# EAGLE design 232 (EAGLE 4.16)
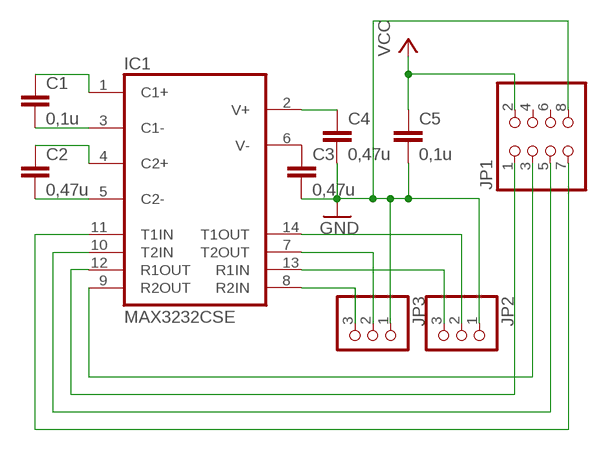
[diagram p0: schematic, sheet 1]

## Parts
C1  0,1u  C-EUC1206  [C1206]
C2  0,47u  C-EUC1206  [C1206]
C3  0,47u  C-EUC1206  [C1206]
C4  0,47u  C-EUC1206  [C1206]
C5  0,1u  C-EUC1206  [C1206]
IC1  MAX3232CSE  [SO16]
JP1  PINHD-2X4  [2X04]
JP2  PINHD-1X3  [1X03]
JP3  PINHD-1X3  [1X03]

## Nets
GND: C3.2 C4.2 C5.2 JP1.8 JP2.1 JP3.1
N$1: C1.2 IC1.3(C1-)
N$2: C1.1 IC1.1(C1+)
N$3: C2.2 IC1.5(C2-)
N$4: C2.1 IC1.4(C2+)
N$5: C4.1 IC1.2(V+)
N$6: C3.1 IC1.6(V-)
N$7: IC1.12(R1OUT) JP1.1
N$8: IC1.9(R2OUT) JP1.3
N$10: IC1.14(T1OUT) JP2.2
N$11: IC1.13(R1IN) JP2.3
N$12: IC1.11(T1IN) JP1.7
N$13: IC1.10(T2IN) JP1.5
N$14: IC1.7(T2OUT) JP3.2
N$15: IC1.8(R2IN) JP3.3
VCC: C5.1 JP1.2
Unconnected: JP1.4 JP1.6

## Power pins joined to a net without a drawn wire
GND: IC1.15(GND)
VCC: IC1.16(VCC)

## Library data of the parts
C1-C5 = rcl:C-EU: CAPACITOR, European symbol
IC1 = maxim:MAX3232*: True RS-232 Transceivers 3.0V to 5.5V, Low-Power up to 1Mbps, Using Four 0.1µF External Capacitors Source: http://pdfserv.maxim-ic.com/en/ds/MAX3222-MAX3241.pdf
JP1 = pinhead:PINHD-2X4: PIN HEADER
JP2 JP3 = pinhead:PINHD-1X3: PIN HEADER

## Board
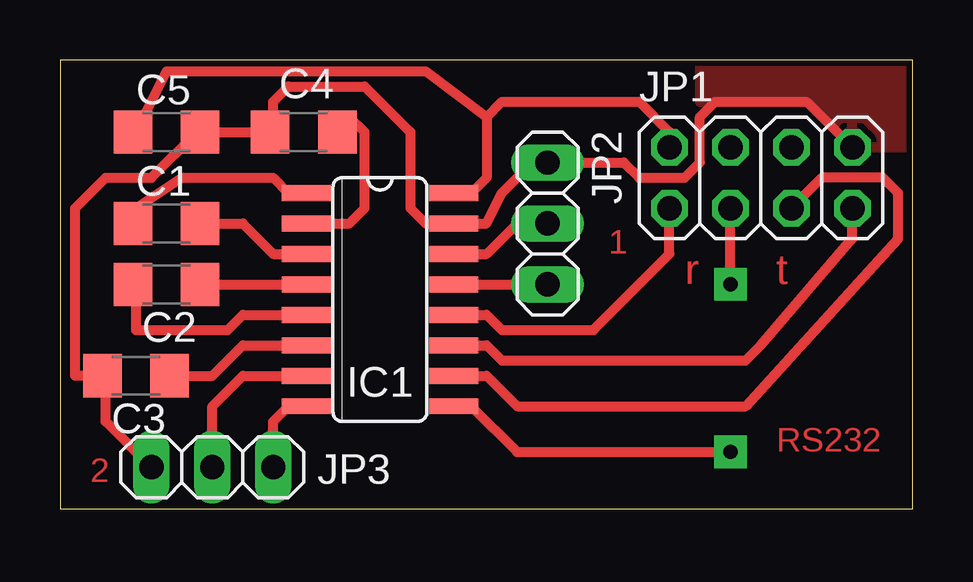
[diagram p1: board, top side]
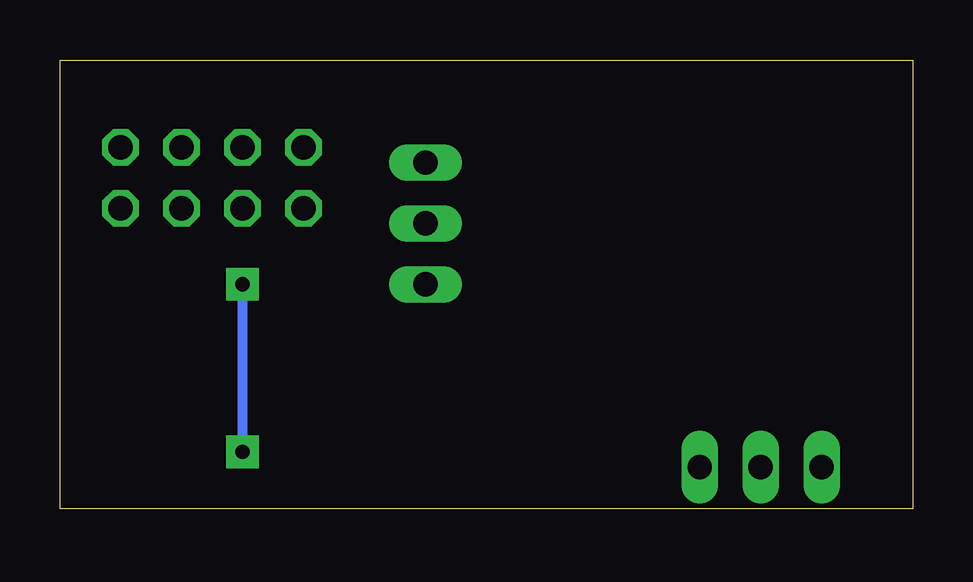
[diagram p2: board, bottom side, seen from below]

Size 35.54 x 18.72 mm. Coordinates in mm from the lower left corner, seen from the top.
Outline: 0,0 35.54,0 35.54,18.72 0,18.72 0,0
Copper layers (1*16): Top 0.035mm / dielectric 1.5mm / Bottom 0.035mm
Design rules "default": minimum track width 10mil, minimum drill 24mil, track to track 8mil, track to pad 8mil, pad to pad 8mil, via to via 8mil, smd to smd 8mil, copper to edge 10mil, drill to drill 8mil, minimum pad ring 10mil, minimum via ring 15mil, stop-mask expansion 4mil, vias tented up to drill 0mil, thermal gap 10mil

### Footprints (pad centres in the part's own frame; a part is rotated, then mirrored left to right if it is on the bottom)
C1206 = smd 1.6 x 1.8: 1 -1.4,0; 2 1.4,0
SO16 = smd 0.66 x 2.032: 1 -4.445,-3.073; 2 -3.175,-3.073; 3 -1.905,-3.073; 4 -0.635,-3.073; 5 0.635,-3.073; 6 1.905,-3.073; 7 3.175,-3.073; 8 4.445,-3.073; 9 4.445,3.073; 10 3.175,3.073; 11 1.905,3.073; 12 0.635,3.073; 13 -0.635,3.073; 14 -1.905,3.073; 15 -3.175,3.073; 16 -4.445,3.073
2X04 = drill 1.016 octagon: 1 -3.81,-1.27; 2 -3.81,1.27; 3 -1.27,-1.27; 4 -1.27,1.27; 5 1.27,-1.27; 6 1.27,1.27; 7 3.81,-1.27; 8 3.81,1.27
1X03 = drill 1.016 long: 1 -2.54,0; 2 0,0; 3 2.54,0

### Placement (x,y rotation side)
C1  4.44,11.9 0 top
C2  4.44,9.36 180 top
C3  3.17,5.55 180 top
C4  10.15,15.71 180 top
C5  4.44,15.71 0 top
IC1  13.33,8.73 270 top
JP1  29.21,13.81 0 top
JP2  20.32,11.9 270 top
JP3  6.35,1.74 0 top

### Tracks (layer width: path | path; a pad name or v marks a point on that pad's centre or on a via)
GND
  Top 0.406: JP1.8 31.11,16.98 27.3,16.98 26.67,16.34 26.67,14.44 26.03,13.81 24.12,13.81 23.49,14.44 JP2.1 19.68,14.44 18.41,13.17 17.78,11.9 IC1.15 15.24,11.9 14.6,12.54 14.6,15.71 12.7,17.61 9.52,17.61 8.88,16.98 8.88,15.71 C4.2 C5.2 5.71,15.71 3.81,13.81 1.9,13.81 0.63,12.54 0.63,5.55 1.9,5.55 | JP3.1 1.9,3.64 1.9,5.55 | 1.9,5.55 C3.2
  pour Top: 33.02,15.08 36.19,15.08 36.19,19.52 26.67,19.52 26.67,16.98 31.11,16.98
N$1
  Top 0.406: IC1.3 8.88,10.63 7.62,11.9 C1.2 6.35,11.9
N$2
  Top 0.406: 10.79,13.17 IC1.1 9.52,13.17 8.88,13.81 5.07,13.81 3.17,12.54 3.17,11.9 C1.1
N$3
  Top 0.406: IC1.5 7.62,8.09 6.98,7.46 3.17,7.46 3.17,9.36 C2.2
N$4
  Top 0.406: 6.35,9.36 C2.1 IC1.4
N$5
  Top 0.406: IC1.2 12.06,11.9 12.7,12.54 12.7,15.71 12.06,16.34 C4.1
N$6
  Top 0.406: IC1.6 7.62,6.82 6.35,5.55 C3.1
N$7
  Top 0.406: IC1.12 17.78,8.09 18.41,7.46 22.22,7.46 25.4,10.63 JP1.1
N$8  (via drill 0.6)
  Top 0.406: v27.94,9.36 JP1.3 | v27.94,2.38 19.05,2.38 17.14,4.28 IC1.9
  Bottom 0.406: v27.94,2.38 v27.94,9.36
N$10
  Top 0.406: JP2.2 19.05,11.9 17.78,10.63 IC1.14
N$11
  Top 0.406: IC1.13 JP2.3
N$12
  Top 0.406: JP1.7 33.02,11.27 29.21,6.82 28.57,6.18 18.41,6.18 17.78,6.82 IC1.11
N$13
  Top 0.406: JP1.5 31.75,13.81 34.29,13.81 34.92,13.17 34.92,11.27 28.57,4.28 19.05,4.28 17.78,5.55 IC1.10
N$14
  Top 0.406: JP3.2 6.35,4.28 7.62,5.55 IC1.7
N$15
  Top 0.406: JP3.3 8.88,3.64 9.52,4.28 IC1.8
VCC
  Top 0.406: JP1.2 25.4,15.71 24.12,16.98 18.41,16.98 17.78,16.34 | 17.78,16.34 17.78,13.81 17.14,13.17 IC1.16 | C5.1 3.17,15.71 4.44,18.25 15.24,18.25 17.78,16.34

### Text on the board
Top: 1 | r | t | RS232 | 2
